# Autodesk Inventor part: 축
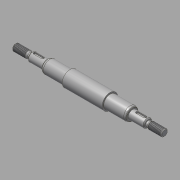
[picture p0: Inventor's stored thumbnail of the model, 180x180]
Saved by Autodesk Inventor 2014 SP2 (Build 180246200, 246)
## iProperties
Created: 2015-11
Part Number: 축
Material: 강철, 연강
Document SubType Name: Modeling
Designer: mduedu
Density: 1 g/cm^3
Appearance: 강철
Author: mduedu
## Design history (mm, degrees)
sketch "스케치1"
  geometry: L1 (-86, 0)-(86, 0); L2 (-86, 0)-(-86, 4); L3 (-86, 4)-(-70.732, 4); L4 (-70.732, 4)-(-69, 3); L5 (-69, 3)-(-67, 3); L6 (-67, 3)-(-67, 5); L7 (-67, 5)-(-49, 5); L8 (-49, 5)-(-49, 6.55); L9 (-47.355, 7.5)-(-23, 7.5); L10 (-23, 7.5)-(-23, 9); L11 (0, 0)-(0, 9); L12 (86, 4)-(70.732, 4); L13 (70.732, 4)-(69, 3); L14 (69, 3)-(67, 3); L15 (67, 3)-(67, 5); L16 (67, 5)-(49, 5); L17 (23, 7.5)-(23, 9); L18 (86, 0)-(86, 4); L19 (-23, 9)-(23, 9); L20 (-49, 6.55)-(-47.355, 7.5); L21 (47.355, 7.5)-(23, 7.5); L22 (49, 6.55)-(47.355, 7.5); L23 (49, 5)-(49, 6.55); 1 further point
  constraints: 46 end point, 10 symmetric about line, 6 perpendicular, 5 parallel, 2 midpoint, 1 coincident, 1 horizontal
  dimensions: "d0" = 172 distance of L1.start L1.end (derived); "d1" = 8 diameter of L3 L1; "d2" = 30 deg angle of L4 L5; "d3" = 6 diameter of L5 L1; "d4" = 10 diameter of L7 L1; "d5" = 15 diameter of L9 L1; "d6" = 18 diameter of L19 L1; "d8" = 18 distance of L6.end L7.end; "d9" = 46 distance of L10.end L17.end; "d10" = 2 distance of L4.end L5.end; "d11" = 17 distance from line of L4.end L2; "d16" = 13.1 diameter of L8.end L1; "d17" = 30 deg angle of L20 L9; "d18" = 26 distance between parallel lines of L10 L8
revolve "회전1" sketch "스케치1" stored, may be unused: angle "d12" = 90 deg
chamfer "모따기1" distance "d13" = 1; stored, may be unused: second distance "d14" = 2, angle "d15" = 45 deg
fillet "모깎기1" dims "d19" = 4, "d20" = 0.5
node "작업 평면1"
sketch "스케치2" dims "d23" = 12
  geometry: L1 (-5.5, 1.5)-(3.5, 1.5); L2 (3.5, 1.5)-(3.5, -1.5); L3 (3.5, -1.5)-(-5.5, -1.5); L4 (-5.5, -1.5)-(-5.5, 1.5); L5 (-9, -4)-(-9, 4) reference; 3 further points
  constraints: 8 end point, 2 midpoint, 2 parallel, 2 vertical alignment, 1 horizontal, 1 perpendicular, 4 other
  dimensions: "d21" = 3 distance between parallel lines of L3 L1; "d24" = 2 dimension on L5
extrude "돌출1" cut sketch "스케치2" distance "d25" = 1.8; taper "d26" = 0 deg
feature "스레드1" dims "d27" = 10, "d28" = 0
feature "스레드2" dims "d29" = 10, "d30" = 0
chamfer "모따기2" distance "d31" = 1; stored, may be unused: second distance "d32" = 2, angle "d33" = 45 deg
fillet "모깎기2" dims "d34" = 0.3
node "솔리드1"
mirror "대칭1"
